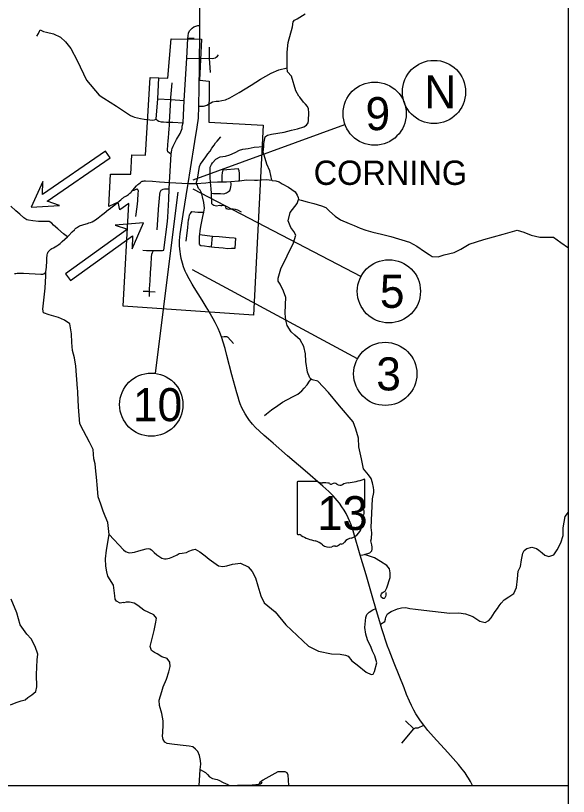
# Model space of a CAD drawing. Extents: x 2025369 to 2161369, y 549489 to 637489.
# Drawn here: x 2081050 to 2092420, y 571334 to 587393 of the extents above; entities that cross this region are included whole.
import ezdxf

# ---------------------------------------------------------------- set-up
doc = ezdxf.new("R2010")
doc.units = 0
for name, color, linetype in [('GM_X_City_Street', 7, 'Continuous'), ('GM_X_Corporation', 7, 'Continuous'), ('GM_X_Corporation_Text', 7, 'Continuous'), ('GM_X_County_Road', 7, 'Continuous'), ('GM_X_State_Route', 7, 'Continuous'), ('GM_X_State_Shield', 7, 'Continuous'), ('GM_X_Township_Road', 7, 'Continuous'), ('GM_X_Township_Subdivision', 7, 'Continuous'), ('SH_Text', 7, 'Continuous')]:
    doc.layers.add(name, color=color, linetype=linetype)

msp = doc.modelspace()

# ---------------------------------------------------------------- linework, layer by layer
at = {"layer": 'GM_X_City_Street'}
for points in [[(2084494, 585190), (2084518, 585646), (2084574, 586515), (2084593, 586920)], [(2084574, 586515), (2084834, 586509)], [(2083943, 585260), (2083972, 585679), (2083998, 586114)], [(2084245, 585709), (2084268, 586010)], [(2083972, 585679), (2084242, 585667), (2084518, 585646)], [(2084208, 585072), (2084212, 585125), (2084212, 585203), (2084242, 585667), (2084245, 585709)], [(2084821, 585531), (2084915, 585532), (2084944, 585537), (2084980, 585549), (2085101, 585618), (2085176, 585632), (2085221, 585632)], [(2083764, 585253), (2083861, 585244), (2083907, 585247), (2083943, 585260), (2083960, 585240), (2083993, 585223), (2084041, 585208), (2084091, 585205), (2084155, 585204)], [(2084155, 585204), (2084212, 585203), (2084282, 585200), (2084494, 585190)], [(2084188, 584811), (2084194, 584883), (2084199, 584971), (2084208, 585072)], [(2084250, 584542), (2084265, 584631), (2084272, 584662), (2084290, 584708), (2084360, 584842), (2084434, 584966), (2084474, 585069), (2084479, 585122), (2084494, 585190)], [(2084966, 584488), (2084966, 584489), (2085004, 584549), (2085053, 584606), (2085089, 584669), (2085131, 584730), (2085164, 584775), (2085195, 584814), (2085269, 584899)], [(2084250, 584542), (2084212, 584565), (2084184, 584590), (2084174, 584616), (2084182, 584744), (2084188, 584811)], [(2085053, 584279), (2085076, 584328), (2085103, 584363), (2085170, 584438), (2085256, 584486), (2085366, 584503), (2085454, 584529), (2085568, 584576), (2085658, 584625), (2085722, 584647), (2085834, 584660), (2085955, 584688), (2086155, 584701)], [(2084209, 583827), (2084209, 583829), (2084215, 583962), (2084250, 584542)], [(2084761, 583943), (2084789, 584033), (2084796, 584072), (2084812, 584161), (2084831, 584290), (2084850, 584340), (2084906, 584416), (2084964, 584485), (2084966, 584488)], [(2085083, 583520), (2085076, 583743), (2085073, 583829), (2085060, 583964), (2085051, 584065), (2085053, 584279)], [(2085319, 584220), (2085628, 584247)], [(2085657, 583996), (2085655, 584151), (2085646, 584197), (2085628, 584247)], [(2085302, 583975), (2085302, 584106), (2085307, 584160), (2085319, 584220)], [(2084598, 583939), (2084761, 583943), (2084960, 583956), (2085060, 583964), (2085201, 583975), (2085302, 583975), (2085391, 583976), (2085476, 583980), (2085487, 583980), (2085625, 583992), (2085657, 583996), (2085797, 584013), (2085963, 584009), (2086025, 584009), (2086089, 584014)], [(2084834, 582684), (2084833, 582782), (2084835, 582860), (2084838, 582889), (2084846, 582975), (2084865, 583087), (2084899, 583261), (2084922, 583350), (2084934, 583431), (2084919, 583549), (2084895, 583669), (2084874, 583747), (2084848, 583802), (2084812, 583839), (2084796, 583872), (2084788, 583909), (2084761, 583943)], [(2085076, 583743), (2085122, 583732), (2085208, 583732), (2085264, 583732), (2085332, 583729), (2085386, 583747), (2085429, 583772), (2085458, 583799), (2085467, 583835), (2085476, 583868), (2085485, 583910), (2085485, 583926), (2085476, 583980)], [(2083526, 583262), (2083550, 583459), (2083562, 583580), (2083573, 583741), (2083576, 583781), (2083575, 583790), (2083574, 583795), (2083571, 583804), (2083567, 583809), (2083561, 583815), (2083555, 583819), (2083548, 583820), (2083540, 583820), (2083531, 583819), (2083523, 583816), (2083497, 583803), (2083485, 583797), (2083480, 583797), (2083472, 583798), (2083462, 583803)], [(2083989, 583413), (2084016, 583711), (2084025, 583764), (2084028, 583776), (2084034, 583790), (2084043, 583801), (2084057, 583811), (2084070, 583819), (2084083, 583824), (2084110, 583828), (2084209, 583827)], [(2084200, 583617), (2084209, 583827)], [(2084182, 583249), (2084194, 583496), (2084200, 583617)], [(2085083, 583520), (2085126, 583491), (2085185, 583481), (2085242, 583493), (2085268, 583487), (2085292, 583488), (2085324, 583493), (2085340, 583491), (2085357, 583482), (2085376, 583426)], [(2083963, 582989), (2083987, 583399), (2083989, 583413)], [(2084609, 583198), (2084610, 583201), (2084618, 583249), (2084629, 583288), (2084635, 583308)], [(2084635, 583308), (2084645, 583320), (2084673, 583361), (2084796, 583352), (2084922, 583350)], [(2085376, 583426), (2085386, 583428), (2085426, 583415), (2085470, 583416), (2085528, 583416), (2085563, 583409), (2085617, 583396), (2085690, 583358)], [(2084098, 582572), (2084177, 583160), (2084182, 583249)], [(2084556, 582752), (2084592, 583038), (2084609, 583197), (2084609, 583198)], [(2084838, 582889), (2085091, 582857), (2085099, 582857), (2085235, 582851), (2085444, 582832), (2085546, 582823), (2085578, 582814)], [(2085076, 582640), (2085099, 582857)], [(2085568, 582613), (2085578, 582814)], [(2084834, 582684), (2084862, 582664), (2084934, 582658), (2085027, 582647)], [(2085027, 582647), (2085029, 582647), (2085039, 582645), (2085076, 582640), (2085143, 582630), (2085322, 582617), (2085408, 582603), (2085488, 582609), (2085568, 582613)], [(2083670, 582568), (2083744, 582560), (2083844, 582559), (2083889, 582559), (2083931, 582559)], [(2083807, 581774), (2083815, 581937), (2083825, 582105), (2083836, 582272), (2083842, 582424), (2083852, 582487), (2083864, 582519), (2083889, 582559)], [(2083931, 582559), (2083943, 582559), (2084021, 582559), (2084074, 582563), (2084098, 582572)], [(2083676, 581728), (2083775, 581723), (2083805, 581721)], [(2083802, 581615), (2083805, 581721), (2083806, 581746), (2083807, 581772), (2083807, 581774)], [(2083805, 581721), (2083923, 581715)]]:
    msp.add_lwpolyline(points, dxfattribs=at)
at = {"layer": 'GM_X_Corporation'}
msp.add_lwpolyline([(2084872, 586908), (2084834, 586068), (2085030, 586045), (2085022, 585199), (2086139, 585142), (2085943, 581234), (2083260, 581415), (2083382, 583526), (2083193, 583399), (2083159, 583558), (2082966, 583469), (2083005, 584133), (2083420, 584135), (2083443, 584532), (2083721, 584525), (2083815, 586122), (2084180, 586107), (2084248, 586914)], close=True, dxfattribs=at)
at = {"layer": 'GM_X_County_Road'}
for points in [[(2086089, 584014), (2086211, 584024), (2086320, 584007), (2086327, 584005), (2086401, 583993), (2086469, 583977), (2086533, 583936), (2086666, 583862), (2086798, 583771), (2086844, 583703), (2086862, 583653), (2086871, 583608), (2086923, 583594), (2087047, 583564), (2087187, 583527), (2087339, 583482), (2087431, 583446), (2087505, 583370), (2087626, 583265), (2087730, 583192), (2087914, 583115), (2088016, 583077), (2088139, 583018), (2088253, 582980), (2088401, 582937), (2088579, 582898), (2088767, 582850), (2089149, 582732), (2089304, 582651), (2089458, 582542), (2089556, 582478), (2089620, 582441), (2089744, 582429), (2089868, 582474), (2090068, 582518), (2090205, 582589), (2090381, 582693), (2090684, 582786), (2091081, 582899), (2091367, 582980), (2091501, 582937), (2091653, 582874), (2091831, 582836), (2092113, 582833), (2092265, 582724), (2092420, 582615)], [(2082328, 579666), (2082326, 579720), (2082292, 580185), (2082259, 580356), (2082217, 580502), (2082206, 580670), (2082201, 580845), (2082166, 581055), (2082056, 581126), (2081934, 581185), (2081742, 581241), (2081624, 581278), (2081613, 581356), (2081658, 581785), (2081669, 582040), (2081673, 582132)], [(2084827, 571561), (2084836, 571773), (2084845, 571888), (2084857, 571996), (2084856, 572075), (2084830, 572175), (2084797, 572256), (2084750, 572308), (2084692, 572353), (2084623, 572367), (2084433, 572385), (2084260, 572408), (2084169, 572422), (2084122, 572446), (2084086, 572503), (2084068, 572569), (2084078, 572650), (2084088, 572806), (2084084, 572887), (2084056, 573036), (2084007, 573206), (2084004, 573312), (2084055, 573488), (2084087, 573586), (2084156, 573748), (2084200, 573895), (2084229, 574005), (2084221, 574093), (2084164, 574167), (2084060, 574204), (2083960, 574266), (2083906, 574293), (2083846, 574337), (2083817, 574419), (2083898, 574746), (2083937, 574920), (2083945, 574998), (2083890, 575066), (2083686, 575165), (2083567, 575257), (2083490, 575310), (2083392, 575329), (2083322, 575329), (2083273, 575317), (2083266, 575319), (2083198, 575311), (2083126, 575348), (2083099, 575388), (2083091, 575462), (2083062, 575675), (2082946, 575862), (2082924, 575950), (2082908, 576067), (2082902, 576218), (2082921, 576397), (2082977, 576719), (2082959, 576846), (2082950, 576968), (2082894, 577096), (2082849, 577197), (2082805, 577343), (2082748, 577498), (2082731, 577668), (2082716, 577899), (2082702, 578023), (2082683, 578171), (2082657, 578274), (2082642, 578470), (2082569, 578617), (2082448, 578852), (2082372, 578994), (2082342, 579343), (2082330, 579631), (2082328, 579666)]]:
    msp.add_lwpolyline(points, dxfattribs=at)
at = {"layer": 'GM_X_State_Route'}
for points in [[(2084836, 586929), (2084837, 587191), (2084841, 587479), (2084841, 587586), (2084837, 587678), (2084829, 587773), (2084818, 587851), (2084818, 587856), (2084801, 587932), (2084780, 588014), (2084753, 588098), (2084728, 588159), (2084714, 588192), (2084663, 588297), (2084615, 588381), (2084613, 588384)], [(2084598, 583939), (2084650, 584242), (2084738, 584806), (2084785, 585096), (2084809, 585286), (2084821, 585531), (2084826, 585916), (2084830, 586339), (2084834, 586509), (2084836, 586915), (2084836, 586929)], [(2083258, 583641), (2083279, 583656), (2083328, 583689), (2083371, 583717), (2083402, 583740), (2083418, 583754), (2083434, 583771), (2083449, 583788), (2083462, 583803), (2083534, 583889), (2083563, 583917), (2083585, 583935), (2083609, 583955), (2083629, 583969), (2083641, 583978), (2083656, 583985), (2083671, 583989), (2083695, 583993), (2083720, 583994), (2083864, 583988), (2084008, 583977)], [(2084008, 583977), (2084215, 583962), (2084598, 583939)], [(2085002, 581348), (2084970, 581400), (2084887, 581537), (2084726, 581799), (2084680, 581871), (2084619, 581982), (2084566, 582083), (2084539, 582139), (2084527, 582173), (2084505, 582229), (2084481, 582304), (2084457, 582396), (2084441, 582483), (2084433, 582543), (2084428, 582589), (2084423, 582662), (2084423, 582765), (2084428, 582836), (2084436, 582904), (2084447, 582996), (2084497, 583300), (2084591, 583900), (2084598, 583939)], [(2082971, 583412), (2083037, 583461), (2083092, 583503), (2083137, 583539), (2083186, 583583), (2083187, 583584), (2083214, 583606), (2083243, 583629), (2083258, 583641)], [(2081029, 582088), (2081053, 582091), (2081080, 582093), (2081114, 582095), (2081149, 582095), (2081211, 582093), (2081569, 582074), (2081609, 582076), (2081622, 582079), (2081635, 582083), (2081645, 582090), (2081657, 582102), (2081666, 582113), (2081673, 582132), (2081678, 582165), (2081682, 582223), (2081689, 582340), (2081692, 582380), (2081694, 582420), (2081697, 582453), (2081701, 582476), (2081707, 582497), (2081712, 582512), (2081722, 582534), (2081732, 582548), (2081744, 582561), (2081759, 582576), (2081776, 582589), (2081796, 582601), (2081829, 582619), (2081861, 582636), (2081900, 582657), (2081937, 582685), (2081967, 582708), (2082009, 582745), (2082062, 582792), (2082114, 582840), (2082136, 582861), (2082216, 582944), (2082258, 582989), (2082270, 583001), (2082289, 583019), (2082305, 583030), (2082325, 583045), (2082344, 583056), (2082365, 583067), (2082382, 583075), (2082415, 583086), (2082454, 583099), (2082532, 583120), (2082556, 583128), (2082592, 583140), (2082625, 583152), (2082659, 583169), (2082695, 583192), (2082751, 583236), (2082818, 583290), (2082868, 583330), (2082959, 583403), (2082971, 583412)], [(2090444, 571561), (2090439, 571572), (2090405, 571641), (2090365, 571709), (2090337, 571753), (2090296, 571815), (2090268, 571853), (2090235, 571896), (2090157, 571987), (2089939, 572234), (2089647, 572560), (2089532, 572690), (2089447, 572796), (2089376, 572890), (2089334, 572951), (2089284, 573033), (2089241, 573108), (2089194, 573200), (2089150, 573294), (2089092, 573432), (2089039, 573567), (2088834, 574076), (2088733, 574344), (2088701, 574424), (2088663, 574528), (2088616, 574676), (2088583, 574782), (2088555, 574877), (2088461, 575201), (2088399, 575409), (2088259, 575889), (2088140, 576296), (2088006, 576748), (2087983, 576824), (2087950, 576922), (2087919, 577003), (2087891, 577066), (2087847, 577153), (2087809, 577219), (2087762, 577291), (2087713, 577363), (2087666, 577421), (2087625, 577471), (2087580, 577519), (2087494, 577602), (2087370, 577714), (2087006, 578028), (2086644, 578340), (2086346, 578599), (2086249, 578684), (2086162, 578758), (2086065, 578845), (2085987, 578921), (2085924, 578992), (2085896, 579024), (2085862, 579068), (2085818, 579130), (2085774, 579201), (2085740, 579261), (2085706, 579329), (2085671, 579411), (2085650, 579467), (2085625, 579547), (2085599, 579633), (2085500, 580005), (2085395, 580400), (2085358, 580546), (2085286, 580783), (2085251, 580875), (2085216, 580956), (2085184, 581026), (2085157, 581080), (2085116, 581156), (2085032, 581299), (2085002, 581348)]]:
    msp.add_lwpolyline(points, dxfattribs=at)
at = {"layer": 'GM_X_State_Shield'}
for p, q in [((2087263, 577813), (2086855, 577813)), ((2088234, 577286), (2088234, 577839)), ((2086841, 577795), (2086841, 576738)), ((2088233, 577287), (2088234, 577286))]:
    msp.add_line(p, q, dxfattribs=at)
for centre, radius, start, end in [((2086857, 577797), 16.1, 98.1301, 188.1301), ((2087360, 577936), 156, 231.6195, 271.1119), ((2087738, 579253), 1476, 275.8445, 288.9065), ((2088218, 577841), 15.5, 351.8621, 97.738), ((2087412, 577220), 562, 80.4867, 94.9883), ((2087539, 577802), 45.1, 219.7921, 297.1024), ((2087605, 577680), 93.8, 54.4667, 119.1411), ((2087727, 577848), 113, 233.8562, 294.8282), ((2087926, 577490), 297, 97.3462, 120.7689), ((2088230, 577246), 24, 107.944, 210.337), ((2088077, 577176), 144, 340.033, 23.6496), ((2088217, 577284), 16.6, 289.6038, 7.7341), ((2087820, 576985), 369, 292.3089, 8.9858), ((2088289, 577055), 105, 136.8065, 186.9296), ((2086857, 576736), 16.3, 171.9584, 258.3066), ((2086860, 576844), 124, 267.339, 280.6039), ((2086885, 576677), 44.8, 29.7484, 93.2717), ((2087451, 577627), 1066, 240.4129, 257.1985), ((2087133, 576263), 334, 47.1842, 75.836), ((2087720, 576636), 119, 282.8732, 323.2771), ((2087976, 576441), 202, 94.4031, 142.5768), ((2087494, 576672), 212, 230.7004, 286.2918), ((2087616, 576307), 174, 85.6951, 111.2099), ((2087631, 576593), 113, 268.777, 315.5493), ((2087733, 576490), 31.8, 65.7517, 132.6484)]:
    msp.add_arc(centre, radius, start, end, dxfattribs=at)
at = {"layer": 'GM_X_Township_Road'}
for points in [[(2086192, 584904), (2086232, 584937), (2086316, 584952), (2086576, 584999), (2086728, 585034), (2086850, 585062), (2086978, 585105), (2087030, 585143), (2087065, 585185), (2087075, 585235), (2087078, 585393), (2087072, 585474), (2087057, 585522), (2087016, 585572), (2086973, 585616), (2086894, 585719), (2086877, 585733), (2086812, 585848), (2086728, 586145), (2086644, 586240), (2086633, 586320), (2086635, 586640), (2086659, 586842), (2086742, 587162), (2086759, 587264), (2086789, 587301), (2086842, 587329), (2087004, 587430)], [(2081486, 586968), (2081520, 587022), (2081540, 587070), (2081555, 587100), (2081626, 587066), (2081688, 587053), (2081830, 587019), (2081973, 586947), (2082076, 586854), (2082187, 586715), (2082313, 586468), (2082506, 586063), (2082769, 585758), (2082864, 585693), (2083123, 585529), (2083413, 585338), (2083460, 585315), (2083497, 585305), (2083617, 585277), (2083693, 585260), (2083764, 585253)], [(2085221, 585632), (2085233, 585632), (2085295, 585648), (2085366, 585664), (2085456, 585700), (2085651, 585810), (2085896, 585961), (2086089, 586089), (2086307, 586206), (2086466, 586279), (2086633, 586320)], [(2086320, 584007), (2086282, 584197), (2086215, 584339), (2086161, 584522), (2086142, 584587), (2086155, 584701), (2086157, 584763), (2086185, 584899), (2086192, 584904)], [(2088140, 576296), (2088191, 576304), (2088227, 576306), (2088334, 576342), (2088374, 576385), (2088384, 576420), (2088386, 576462), (2088376, 576509), (2088357, 576588), (2088372, 576640), (2088374, 576754), (2088363, 576861), (2088394, 577456), (2088417, 577586), (2088419, 577631), (2088413, 577685), (2088394, 577786), (2088360, 577875), (2088309, 577947), (2088207, 578072), (2088164, 578274), (2088111, 578523), (2088100, 578701), (2088051, 578884), (2087992, 579041), (2087715, 579364), (2087484, 579642), (2087263, 579877), (2087151, 579900), (2087130, 579916), (2087099, 579942), (2087056, 580058), (2087017, 580279), (2087013, 580433), (2086976, 580588), (2086905, 580724), (2086795, 580819), (2086715, 580889), (2086638, 581018), (2086606, 581130), (2086595, 581267), (2086600, 581453), (2086606, 581597), (2086559, 581728), (2086493, 581868), (2086448, 581931), (2086448, 581991), (2086505, 582187), (2086636, 582455), (2086765, 582721), (2086816, 582875), (2086776, 582951), (2086709, 583032), (2086653, 583174), (2086700, 583345), (2086839, 583530), (2086871, 583608)], [(2082114, 582840), (2082037, 582903), (2081920, 583010), (2081831, 583085), (2081795, 583125), (2081743, 583157), (2081637, 583158), (2081523, 583156), (2081405, 583173), (2081313, 583189), (2081283, 583195), (2081221, 583236), (2081137, 583306), (2081052, 583381), (2080952, 583475)], [(2085286, 580783), (2085340, 580792), (2085357, 580794), (2085369, 580794), (2085379, 580794), (2085392, 580792), (2085403, 580787), (2085418, 580776), (2085533, 580646)], [(2086167, 579168), (2086209, 579200), (2086314, 579282), (2086444, 579371), (2086541, 579445), (2086631, 579493), (2086771, 579566), (2086853, 579608), (2086938, 579672), (2086986, 579730), (2087046, 579802), (2087097, 579876), (2087130, 579916)], [(2088555, 574877), (2088646, 574928), (2088661, 574981), (2088663, 575023), (2088699, 575091), (2088776, 575139), (2088902, 575194), (2088985, 575209), (2089078, 575217), (2089158, 575199), (2089276, 575184), (2089450, 575161), (2089981, 575099), (2090167, 575112), (2090303, 575091), (2090453, 575035), (2090602, 574938), (2090710, 574909), (2090781, 574953), (2090829, 575007), (2090903, 575115), (2090958, 575193), (2090960, 575195), (2090996, 575251), (2091034, 575311), (2091101, 575375), (2091197, 575435), (2091299, 575506), (2091356, 575630), (2091373, 575807), (2091388, 575963), (2091432, 576061), (2091455, 576199), (2091483, 576333), (2091512, 576389), (2091564, 576435), (2091670, 576459), (2091764, 576435), (2091812, 576400), (2091882, 576340), (2091935, 576298), (2092015, 576271), (2092120, 576301), (2092186, 576405), (2092263, 576547), (2092313, 576699), (2092312, 576855), (2092355, 577090), (2092420, 577179)], [(2082977, 576719), (2083267, 576403), (2083313, 576369), (2083365, 576351), (2083399, 576345), (2083493, 576354), (2083585, 576384), (2083661, 576408), (2083732, 576424), (2083782, 576430), (2083812, 576427), (2083848, 576405), (2083899, 576353), (2083953, 576299), (2084059, 576232), (2084111, 576222), (2084147, 576222), (2084213, 576233), (2084285, 576261), (2084371, 576305), (2084417, 576327), (2084474, 576333), (2084566, 576348), (2084616, 576378), (2084686, 576408), (2084740, 576420), (2084842, 576365), (2084946, 576283), (2085029, 576210), (2085223, 576079), (2085315, 576063), (2085397, 576078), (2085509, 576108), (2085675, 576132), (2085835, 576057), (2085917, 575956), (2085986, 575826), (2086033, 575665), (2086096, 575460), (2086162, 575314), (2086386, 575132), (2086606, 574859), (2087073, 574424), (2087280, 574320), (2087545, 574266), (2087725, 574256), (2087837, 574237), (2087891, 574217), (2087967, 574123), (2088075, 574037), (2088262, 573891), (2088366, 573844), (2088402, 573846), (2088409, 573858), (2088435, 573902), (2088478, 574081), (2088442, 574222), (2088390, 574320), (2088362, 574395), (2088288, 574554), (2088251, 574671), (2088232, 574808), (2088253, 575015), (2088271, 575073), (2088324, 575120), (2088395, 575169), (2088461, 575201)], [(2088664, 575527), (2088662, 575473), (2088656, 575442), (2088644, 575417), (2088629, 575404), (2088608, 575402), (2088575, 575427), (2088563, 575475), (2088573, 575502), (2088588, 575520), (2088611, 575537), (2088652, 575556), (2088683, 575624), (2088755, 575839), (2088757, 575934), (2088741, 576011), (2088686, 576083), (2088556, 576168), (2088432, 576238), (2088227, 576306)], [(2080946, 573214), (2081062, 573265), (2081166, 573299), (2081246, 573319), (2081299, 573369), (2081387, 573423), (2081467, 573488), (2081488, 573589), (2081481, 573843), (2081496, 574140), (2081509, 574262), (2081449, 574418), (2081370, 574575), (2081278, 574672), (2081147, 574860), (2081072, 575109), (2080958, 575390)], [(2089244, 572721), (2089068, 572888)], [(2088997, 572427), (2089244, 572721), (2089254, 572731), (2089262, 572737), (2089277, 572743), (2089291, 572743), (2089312, 572743), (2089328, 572743), (2089447, 572796)], [(2084845, 571888), (2084895, 571861), (2084957, 571826), (2084999, 571784), (2085038, 571735), (2085100, 571700), (2085193, 571680), (2085232, 571668), (2085318, 571619), (2085415, 571577), (2085441, 571561)], [(2086051, 571561), (2086062, 571590), (2086088, 571641), (2086139, 571675), (2086452, 571843), (2086588, 571843), (2086628, 571828), (2086651, 571776), (2086660, 571561)], [(2085608, 571561), (2085620, 571563), (2085917, 571571), (2086063, 571585), (2086084, 571595), (2086111, 571609), (2086119, 571628), (2086119, 571629)], [(2085608, 571561), (2085620, 571563), (2085917, 571571), (2086063, 571585), (2086084, 571595), (2086111, 571609), (2086119, 571628), (2086119, 571629)]]:
    msp.add_lwpolyline(points, dxfattribs=at)
at = {"layer": 'GM_X_Township_Subdivision'}
for points in [[(2084593, 586920), (2084607, 587029), (2084626, 587082), (2084683, 587137), (2084718, 587160), (2084758, 587175), (2084799, 587187), (2084837, 587191)], [(2084726, 586920), (2084593, 586920)], [(2085057, 586222), (2085039, 586517), (2085040, 586746)], [(2084834, 586509), (2085039, 586517), (2085094, 586512), (2085126, 586518), (2085160, 586527), (2085178, 586536), (2085206, 586561), (2085223, 586588)]]:
    msp.add_lwpolyline(points, dxfattribs=at)
at = {"layer": 'SH_Text'}
for p, q in [((2084704, 584016), (2087824, 585154)), ((2084386, 583762), (2083921, 580036)), ((2084695, 583829), (2088156, 582030)), ((2088081, 580333), (2084688, 582164)), ((2092420, 564989), (2092420, 571561))]:
    msp.add_line(p, q, dxfattribs=at)
msp.add_lwpolyline([(2037369, 631489), (2037369, 571561), (2092420, 571561), (2092420, 631489)], dxfattribs=at)
for points in [[(2082992, 584470), (2082898, 584606), (2081606, 583713), (2081613, 583982), (2081372, 583451), (2081954, 583488), (2081700, 583577)], [(2082079, 582080), (2082177, 581945), (2083451, 582864), (2083449, 582595), (2083679, 583131), (2083098, 583082), (2083354, 582998)]]:
    msp.add_lwpolyline(points, close=True, dxfattribs=at)
for centre in [(2089656, 585823), (2088435, 585377), (2088728, 581722), (2088653, 580024), (2083840, 579391)]:
    msp.add_circle(centre, 650, dxfattribs=at)

# ---------------------------------------------------------------- texts
at = {"layer": 'GM_X_Corporation_Text'}
msp.add_text('CORNING', height=500, rotation=0, dxfattribs=at).set_placement((2087180, 583911))
at = {"layer": 'GM_X_State_Shield'}
msp.add_text('13', height=696.1, dxfattribs=at).set_placement((2087256, 576813))
at = {"layer": 'SH_Text'}
for s, p in [('N', (2089455, 585483)), ('9', (2088247, 585037)), ('5', (2088543, 581382)), ('3', (2088469, 579684)), ('10', (2083465, 579051))]:
    msp.add_text(s, height=680, dxfattribs=at).set_placement(p)

doc.saveas('drawing.dxf')
